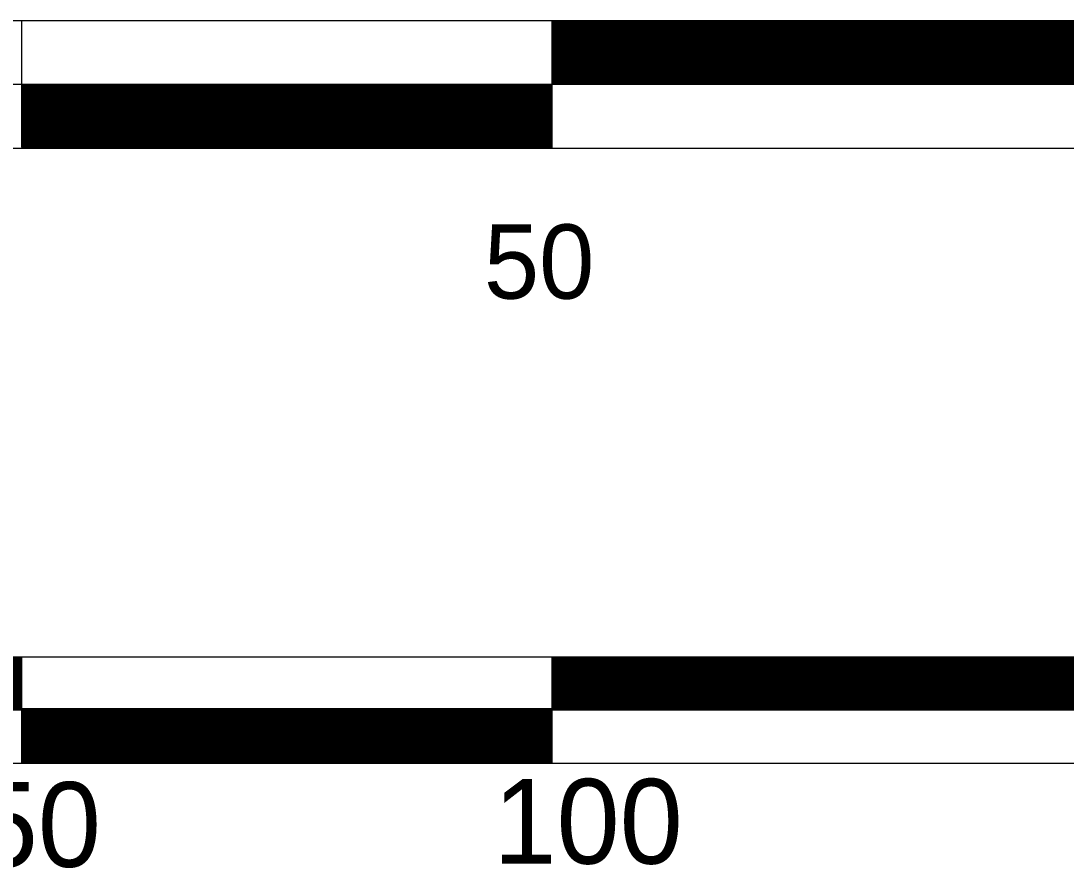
# Model space of a CAD drawing. Extents: x 2147716 to 2176321, y 2125040 to 2131750.
# Drawn here: x 2170015.6 to 2170114.1, y 2129144.1 to 2129224 of the extents above; entities that cross this region are included whole.
import ezdxf

# ---------------------------------------------------------------- set-up
doc = ezdxf.new("R2010")
doc.units = 0
doc.layers.add('MAP DATA', color=7, linetype='Continuous')

msp = doc.modelspace()

# ---------------------------------------------------------------- linework, layer by layer
at = {"layer": 'MAP DATA'}
for p, q in [((2170465.63, 2129223.977), (2169965.629, 2129223.977)), ((2170015.629, 2129223.977), (2170015.629, 2129212.076)), ((2170065.629, 2129223.977), (2170065.629, 2129211.976)), ((2170165.73, 2129223.977), (2170065.629, 2129223.977)), ((2170165.73, 2129223.877), (2170065.629, 2129223.877)), ((2170165.73, 2129223.777), (2170065.629, 2129223.777)), ((2170165.73, 2129223.677), (2170065.629, 2129223.677)), ((2170165.73, 2129223.577), (2170065.629, 2129223.577)), ((2170165.73, 2129223.477), (2170065.629, 2129223.477)), ((2170165.73, 2129223.377), (2170065.629, 2129223.377)), ((2170165.73, 2129223.277), (2170065.629, 2129223.277)), ((2170165.73, 2129223.177), (2170065.629, 2129223.177)), ((2170165.73, 2129223.077), (2170065.629, 2129223.077)), ((2170165.73, 2129222.977), (2170065.629, 2129222.977)), ((2170165.73, 2129222.877), (2170065.629, 2129222.877)), ((2170165.73, 2129222.777), (2170065.629, 2129222.777)), ((2170165.73, 2129222.677), (2170065.629, 2129222.677)), ((2170165.73, 2129222.577), (2170065.629, 2129222.577)), ((2170165.73, 2129222.477), (2170065.629, 2129222.477)), ((2170165.73, 2129222.377), (2170065.629, 2129222.377)), ((2170165.73, 2129222.277), (2170065.629, 2129222.277)), ((2170165.73, 2129222.177), (2170065.629, 2129222.177)), ((2170165.73, 2129222.077), (2170065.629, 2129222.077)), ((2170165.73, 2129221.977), (2170065.629, 2129221.977)), ((2170165.73, 2129221.877), (2170065.629, 2129221.877)), ((2170165.73, 2129221.777), (2170065.629, 2129221.777)), ((2170165.73, 2129221.677), (2170065.629, 2129221.677)), ((2170165.73, 2129221.577), (2170065.629, 2129221.577)), ((2170165.73, 2129221.477), (2170065.629, 2129221.477)), ((2170165.73, 2129221.377), (2170065.629, 2129221.377)), ((2170165.73, 2129221.277), (2170065.629, 2129221.277)), ((2170165.73, 2129221.177), (2170065.629, 2129221.177)), ((2170165.73, 2129221.077), (2170065.629, 2129221.077)), ((2170165.73, 2129220.977), (2170065.629, 2129220.977)), ((2170165.73, 2129220.877), (2170065.629, 2129220.877)), ((2170165.73, 2129220.777), (2170065.629, 2129220.777)), ((2170165.73, 2129220.677), (2170065.629, 2129220.677)), ((2170165.73, 2129220.577), (2170065.629, 2129220.577)), ((2170165.73, 2129220.477), (2170065.629, 2129220.477)), ((2170165.73, 2129220.377), (2170065.629, 2129220.377)), ((2170165.73, 2129220.277), (2170065.629, 2129220.277)), ((2170165.73, 2129220.177), (2170065.629, 2129220.177)), ((2170165.73, 2129220.077), (2170065.629, 2129220.077)), ((2170165.73, 2129219.977), (2170065.629, 2129219.977)), ((2170165.73, 2129219.877), (2170065.629, 2129219.877)), ((2170165.73, 2129219.877), (2170065.629, 2129219.877)), ((2170165.73, 2129219.777), (2170065.629, 2129219.777)), ((2170165.73, 2129219.677), (2170065.629, 2129219.677)), ((2170165.73, 2129219.577), (2170065.629, 2129219.577)), ((2170165.73, 2129219.477), (2170065.629, 2129219.477)), ((2170165.73, 2129219.377), (2170065.629, 2129219.377)), ((2170165.73, 2129219.277), (2170065.629, 2129219.277)), ((2170165.73, 2129219.177), (2170065.629, 2129219.177)), ((2170165.73, 2129219.077), (2170065.629, 2129219.077)), ((2170165.73, 2129218.977), (2170065.629, 2129218.977)), ((2170165.73, 2129218.877), (2170065.629, 2129218.877)), ((2170165.73, 2129218.777), (2170065.629, 2129218.777)), ((2170165.73, 2129218.677), (2170065.629, 2129218.677)), ((2170165.73, 2129218.577), (2170065.629, 2129218.577)), ((2170165.73, 2129218.477), (2170065.629, 2129218.477)), ((2170165.73, 2129218.377), (2170065.629, 2129218.377)), ((2170165.73, 2129218.277), (2170065.629, 2129218.277)), ((2170465.63, 2129217.977), (2169965.729, 2129217.977)), ((2170065.629, 2129217.977), (2170015.629, 2129217.977)), ((2170065.629, 2129217.877), (2170015.629, 2129217.877)), ((2170065.629, 2129217.777), (2170015.629, 2129217.777)), ((2170065.629, 2129217.677), (2170015.629, 2129217.677)), ((2170065.629, 2129217.577), (2170015.629, 2129217.577)), ((2170065.629, 2129217.477), (2170015.629, 2129217.477)), ((2170065.629, 2129217.377), (2170015.629, 2129217.377)), ((2170065.629, 2129217.276), (2170015.629, 2129217.276)), ((2170165.73, 2129218.177), (2170065.629, 2129218.177)), ((2170165.73, 2129218.077), (2170065.629, 2129218.077)), ((2170165.73, 2129217.977), (2170065.629, 2129217.977)), ((2170065.629, 2129217.176), (2170015.629, 2129217.176)), ((2170065.629, 2129217.076), (2170015.629, 2129217.076)), ((2170065.629, 2129216.976), (2170015.629, 2129216.976)), ((2170065.629, 2129216.876), (2170015.629, 2129216.876)), ((2170065.629, 2129216.776), (2170015.629, 2129216.776)), ((2170065.629, 2129216.676), (2170015.629, 2129216.676)), ((2170065.629, 2129216.576), (2170015.629, 2129216.576)), ((2170065.629, 2129216.476), (2170015.629, 2129216.476)), ((2170065.629, 2129216.376), (2170015.629, 2129216.376)), ((2170065.629, 2129216.276), (2170015.629, 2129216.276)), ((2170065.629, 2129216.176), (2170015.629, 2129216.176)), ((2170065.629, 2129216.076), (2170015.629, 2129216.076)), ((2170065.629, 2129215.976), (2170015.629, 2129215.976)), ((2170065.629, 2129215.876), (2170015.629, 2129215.876)), ((2170065.629, 2129215.776), (2170015.629, 2129215.776)), ((2170065.629, 2129215.676), (2170015.629, 2129215.676)), ((2170065.629, 2129215.576), (2170015.629, 2129215.576)), ((2170065.629, 2129215.476), (2170015.629, 2129215.476)), ((2170065.629, 2129215.376), (2170015.629, 2129215.376)), ((2170065.629, 2129215.276), (2170015.629, 2129215.276)), ((2170065.629, 2129215.176), (2170015.629, 2129215.176)), ((2170065.629, 2129215.076), (2170015.629, 2129215.076)), ((2170065.629, 2129214.976), (2170015.629, 2129214.976)), ((2170065.629, 2129214.876), (2170015.629, 2129214.876)), ((2170065.629, 2129214.776), (2170015.629, 2129214.776)), ((2170065.629, 2129214.676), (2170015.629, 2129214.676)), ((2170065.629, 2129214.576), (2170015.629, 2129214.576)), ((2170065.629, 2129214.476), (2170015.629, 2129214.476)), ((2170065.629, 2129214.376), (2170015.629, 2129214.376)), ((2170065.629, 2129214.276), (2170015.629, 2129214.276)), ((2170065.629, 2129214.176), (2170015.629, 2129214.176)), ((2170065.629, 2129214.076), (2170015.629, 2129214.076)), ((2170065.629, 2129213.976), (2170015.629, 2129213.976)), ((2170065.629, 2129213.976), (2170015.629, 2129213.976)), ((2170065.629, 2129213.876), (2170015.629, 2129213.876)), ((2170065.629, 2129213.776), (2170015.629, 2129213.776)), ((2170065.629, 2129213.676), (2170015.629, 2129213.676)), ((2170065.629, 2129213.576), (2170015.629, 2129213.576)), ((2170065.629, 2129213.476), (2170015.629, 2129213.476)), ((2170065.629, 2129213.376), (2170015.629, 2129213.376)), ((2170065.629, 2129213.276), (2170015.629, 2129213.276)), ((2170065.629, 2129213.176), (2170015.629, 2129213.176)), ((2170065.629, 2129213.076), (2170015.629, 2129213.076)), ((2170065.629, 2129212.976), (2170015.629, 2129212.976)), ((2170065.629, 2129212.876), (2170015.629, 2129212.876)), ((2170065.629, 2129212.776), (2170015.629, 2129212.776)), ((2170065.629, 2129212.676), (2170015.629, 2129212.676)), ((2170065.629, 2129212.576), (2170015.629, 2129212.576)), ((2170065.629, 2129212.476), (2170015.629, 2129212.476)), ((2170065.629, 2129212.376), (2170015.629, 2129212.376)), ((2169965.629, 2129211.976), (2170465.63, 2129211.976)), ((2170065.629, 2129212.276), (2170015.629, 2129212.276)), ((2170065.629, 2129212.176), (2170015.629, 2129212.176)), ((2170065.629, 2129212.076), (2170015.629, 2129212.076)), ((2170065.629, 2129211.976), (2170015.629, 2129211.976)), ((2169965.629, 2129163.977), (2170465.63, 2129163.977)), ((2170005.629, 2129163.977), (2170015.629, 2129163.977)), ((2170005.629, 2129163.877), (2170015.629, 2129163.877)), ((2170005.629, 2129163.777), (2170015.629, 2129163.777)), ((2170005.629, 2129163.677), (2170015.629, 2129163.677)), ((2170005.629, 2129163.577), (2170015.629, 2129163.577)), ((2170005.629, 2129163.477), (2170015.629, 2129163.477)), ((2170005.629, 2129163.377), (2170015.629, 2129163.377)), ((2170005.629, 2129163.277), (2170015.629, 2129163.277)), ((2170005.629, 2129163.177), (2170015.629, 2129163.177)), ((2170005.629, 2129163.077), (2170015.629, 2129163.077)), ((2170015.629, 2129163.977), (2170015.629, 2129153.976)), ((2170065.629, 2129163.977), (2170065.629, 2129153.976)), ((2170065.629, 2129163.977), (2170165.63, 2129163.977)), ((2170065.629, 2129163.877), (2170165.63, 2129163.877)), ((2170065.629, 2129163.777), (2170165.63, 2129163.777)), ((2170065.629, 2129163.677), (2170165.63, 2129163.677)), ((2170065.629, 2129163.577), (2170165.63, 2129163.577)), ((2170065.629, 2129163.477), (2170165.63, 2129163.477)), ((2170065.629, 2129163.377), (2170165.63, 2129163.377)), ((2170065.629, 2129163.277), (2170165.63, 2129163.277)), ((2170065.629, 2129163.177), (2170165.63, 2129163.177)), ((2170065.629, 2129163.077), (2170165.63, 2129163.077)), ((2170005.629, 2129162.977), (2170015.629, 2129162.977)), ((2170005.629, 2129162.877), (2170015.629, 2129162.877)), ((2170005.629, 2129162.777), (2170015.629, 2129162.777)), ((2170005.629, 2129162.677), (2170015.629, 2129162.677)), ((2170005.629, 2129162.577), (2170015.629, 2129162.577)), ((2170005.629, 2129162.477), (2170015.629, 2129162.477)), ((2170005.629, 2129162.377), (2170015.629, 2129162.377)), ((2170005.629, 2129162.277), (2170015.629, 2129162.277)), ((2170005.629, 2129162.277), (2170015.629, 2129162.277)), ((2170005.629, 2129162.177), (2170015.629, 2129162.177)), ((2170005.629, 2129162.077), (2170015.629, 2129162.077)), ((2170065.629, 2129162.977), (2170165.63, 2129162.977)), ((2170065.629, 2129162.877), (2170165.63, 2129162.877)), ((2170065.629, 2129162.777), (2170165.63, 2129162.777)), ((2170065.629, 2129162.677), (2170165.63, 2129162.677)), ((2170065.629, 2129162.577), (2170165.63, 2129162.577)), ((2170065.629, 2129162.477), (2170165.63, 2129162.477)), ((2170065.629, 2129162.377), (2170165.63, 2129162.377)), ((2170065.629, 2129162.277), (2170165.63, 2129162.277)), ((2170065.629, 2129162.177), (2170165.63, 2129162.177)), ((2170065.629, 2129162.077), (2170165.63, 2129162.077)), ((2170005.629, 2129161.977), (2170015.629, 2129161.977)), ((2170005.629, 2129161.877), (2170015.629, 2129161.877)), ((2170005.629, 2129161.777), (2170015.629, 2129161.777)), ((2170005.629, 2129161.677), (2170015.629, 2129161.677)), ((2170005.629, 2129161.577), (2170015.629, 2129161.577)), ((2170005.629, 2129161.477), (2170015.629, 2129161.477)), ((2170005.629, 2129161.377), (2170015.629, 2129161.377)), ((2170005.629, 2129161.277), (2170015.629, 2129161.277)), ((2170005.629, 2129161.177), (2170015.629, 2129161.177)), ((2170005.629, 2129161.077), (2170015.629, 2129161.077)), ((2170065.629, 2129161.977), (2170165.63, 2129161.977)), ((2170065.629, 2129161.877), (2170165.63, 2129161.877)), ((2170065.629, 2129161.777), (2170165.63, 2129161.777)), ((2170065.629, 2129161.677), (2170165.63, 2129161.677)), ((2170065.629, 2129161.577), (2170165.63, 2129161.577)), ((2170065.629, 2129161.477), (2170165.63, 2129161.477)), ((2170065.629, 2129161.377), (2170165.63, 2129161.377)), ((2170065.629, 2129161.277), (2170165.63, 2129161.277)), ((2170065.629, 2129161.177), (2170165.63, 2129161.177)), ((2170065.629, 2129161.077), (2170165.63, 2129161.077)), ((2170005.629, 2129160.977), (2170015.629, 2129160.977)), ((2170005.629, 2129160.877), (2170015.629, 2129160.877)), ((2170005.629, 2129160.777), (2170015.629, 2129160.777)), ((2170005.629, 2129160.777), (2170015.629, 2129160.777)), ((2170005.629, 2129160.677), (2170015.629, 2129160.677)), ((2170005.629, 2129160.577), (2170015.629, 2129160.577)), ((2170005.629, 2129160.477), (2170015.629, 2129160.477)), ((2170005.629, 2129160.377), (2170015.629, 2129160.377)), ((2170005.629, 2129160.277), (2170015.629, 2129160.277)), ((2170005.629, 2129160.177), (2170015.629, 2129160.177)), ((2170005.629, 2129160.077), (2170015.629, 2129160.077)), ((2170065.629, 2129160.977), (2170165.63, 2129160.977)), ((2170065.629, 2129160.877), (2170165.63, 2129160.877)), ((2170065.629, 2129160.777), (2170165.63, 2129160.777)), ((2170065.629, 2129160.777), (2170165.63, 2129160.777)), ((2170065.629, 2129160.677), (2170165.63, 2129160.677)), ((2170065.629, 2129160.577), (2170165.63, 2129160.577)), ((2170065.629, 2129160.477), (2170165.63, 2129160.477)), ((2170065.629, 2129160.377), (2170165.63, 2129160.377)), ((2170065.629, 2129160.277), (2170165.63, 2129160.277)), ((2170065.629, 2129160.177), (2170165.63, 2129160.177)), ((2170065.629, 2129160.077), (2170165.63, 2129160.077)), ((2170005.629, 2129159.977), (2170015.629, 2129159.977)), ((2170005.629, 2129159.877), (2170015.629, 2129159.877)), ((2170005.629, 2129159.777), (2170015.629, 2129159.777)), ((2170005.629, 2129159.677), (2170015.629, 2129159.677)), ((2170005.629, 2129159.577), (2170015.629, 2129159.577)), ((2170005.629, 2129159.477), (2170015.629, 2129159.477)), ((2170005.629, 2129159.377), (2170015.629, 2129159.377)), ((2170005.629, 2129159.277), (2170015.629, 2129159.277)), ((2170005.629, 2129159.177), (2170015.629, 2129159.177)), ((2170065.629, 2129159.977), (2170165.63, 2129159.977)), ((2170065.629, 2129159.877), (2170165.63, 2129159.877)), ((2170065.629, 2129159.777), (2170165.63, 2129159.777)), ((2170065.629, 2129159.677), (2170165.63, 2129159.677)), ((2170065.629, 2129159.577), (2170165.63, 2129159.577)), ((2170065.629, 2129159.477), (2170165.63, 2129159.477)), ((2170065.629, 2129159.377), (2170165.63, 2129159.377)), ((2170065.629, 2129159.277), (2170165.63, 2129159.277)), ((2170065.629, 2129159.177), (2170165.63, 2129159.177)), ((2169965.629, 2129158.977), (2170465.63, 2129158.977)), ((2170005.629, 2129159.077), (2170015.629, 2129159.077)), ((2170005.629, 2129158.977), (2170015.629, 2129158.977)), ((2170065.629, 2129159.077), (2170015.629, 2129159.077)), ((2170065.629, 2129158.977), (2170015.629, 2129158.977)), ((2170065.629, 2129158.877), (2170015.629, 2129158.877)), ((2170065.629, 2129158.777), (2170015.629, 2129158.777)), ((2170065.629, 2129158.677), (2170015.629, 2129158.677)), ((2170065.629, 2129158.577), (2170015.629, 2129158.577)), ((2170065.629, 2129158.477), (2170015.629, 2129158.477)), ((2170065.629, 2129158.377), (2170015.629, 2129158.377)), ((2170065.629, 2129158.277), (2170015.629, 2129158.277)), ((2170065.629, 2129158.177), (2170015.629, 2129158.177)), ((2170065.629, 2129159.077), (2170165.63, 2129159.077)), ((2170065.629, 2129158.977), (2170165.63, 2129158.977)), ((2170065.629, 2129158.077), (2170015.629, 2129158.077)), ((2170065.629, 2129157.977), (2170015.629, 2129157.977)), ((2170065.629, 2129157.877), (2170015.629, 2129157.877)), ((2170065.629, 2129157.777), (2170015.629, 2129157.777)), ((2170065.629, 2129157.677), (2170015.629, 2129157.677)), ((2170065.629, 2129157.577), (2170015.629, 2129157.577)), ((2170065.629, 2129157.477), (2170015.629, 2129157.477)), ((2170065.629, 2129157.377), (2170015.629, 2129157.377)), ((2170065.629, 2129157.276), (2170015.629, 2129157.276)), ((2170065.629, 2129157.176), (2170015.629, 2129157.176)), ((2170065.629, 2129157.076), (2170015.629, 2129157.076)), ((2170065.629, 2129156.976), (2170015.629, 2129156.976)), ((2170065.629, 2129156.876), (2170015.629, 2129156.876)), ((2170065.629, 2129156.776), (2170015.629, 2129156.776)), ((2170065.629, 2129156.676), (2170015.629, 2129156.676)), ((2170065.629, 2129156.576), (2170015.629, 2129156.576)), ((2170065.629, 2129156.476), (2170015.629, 2129156.476)), ((2170065.629, 2129156.376), (2170015.629, 2129156.376)), ((2170065.629, 2129156.276), (2170015.629, 2129156.276)), ((2170065.629, 2129156.176), (2170015.629, 2129156.176)), ((2170065.629, 2129156.076), (2170015.629, 2129156.076)), ((2170065.629, 2129155.976), (2170015.629, 2129155.976)), ((2170065.629, 2129155.876), (2170015.629, 2129155.876)), ((2170065.629, 2129155.776), (2170015.629, 2129155.776)), ((2170065.629, 2129155.676), (2170015.629, 2129155.676)), ((2170065.629, 2129155.576), (2170015.629, 2129155.576)), ((2170065.629, 2129155.576), (2170015.629, 2129155.576)), ((2170065.629, 2129155.476), (2170015.629, 2129155.476)), ((2170065.629, 2129155.376), (2170015.629, 2129155.376)), ((2170065.629, 2129155.276), (2170015.629, 2129155.276)), ((2170065.629, 2129155.176), (2170015.629, 2129155.176)), ((2170065.629, 2129155.076), (2170015.629, 2129155.076)), ((2170065.629, 2129154.976), (2170015.629, 2129154.976)), ((2170065.629, 2129154.876), (2170015.629, 2129154.876)), ((2170065.629, 2129154.776), (2170015.629, 2129154.776)), ((2170065.629, 2129154.676), (2170015.629, 2129154.676)), ((2170065.629, 2129154.576), (2170015.629, 2129154.576)), ((2170065.629, 2129154.476), (2170015.629, 2129154.476)), ((2170065.629, 2129154.476), (2170015.629, 2129154.476)), ((2170065.629, 2129154.376), (2170015.629, 2129154.376)), ((2170065.629, 2129154.276), (2170015.629, 2129154.276)), ((2170065.629, 2129154.176), (2170015.629, 2129154.176)), ((2169965.629, 2129153.976), (2170465.63, 2129153.976)), ((2170065.629, 2129154.076), (2170015.629, 2129154.076)), ((2170065.629, 2129153.976), (2170015.629, 2129153.976))]:
    msp.add_line(p, q, dxfattribs=at)

# ---------------------------------------------------------------- texts
for s, height, p in [('50', 7.0002, (2170059.229, 2129197.776)), ('50', 7.9998, (2170011.229, 2129144.176)), ('100', 7.9998, (2170060.129, 2129144.476))]:
    msp.add_text(s, height=height, dxfattribs=at).set_placement(p)

doc.saveas('drawing.dxf')
